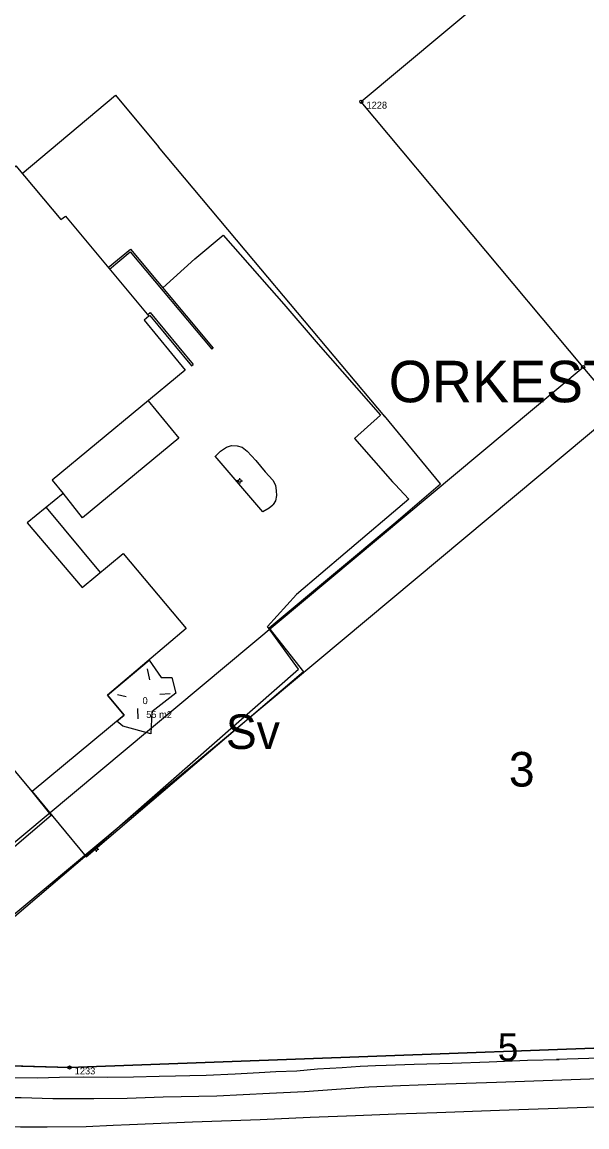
# Model space of a CAD drawing. Extents: x 1517478 to 1518189, y 6494860 to 6495389.
# Drawn here: x 1517838.6 to 1517920.3, y 6494947.7 to 6495107.4 of the extents above; entities that cross this region are included whole.
import ezdxf

# ---------------------------------------------------------------- set-up
doc = ezdxf.new("R2010")
doc.units = 0
for name, color, linetype in [('adress', 7, 'Continuous'), ('allmanbygg_symbollinje', 7, 'Continuous'), ('allmanbyggnad', 7, 'Continuous'), ('allmanbyggnad_nummer', 7, 'Continuous'), ('byggnad_areatext', 7, 'Continuous'), ('fastighetsbeteckning', 7, 'Continuous'), ('gc_vag', 7, 'Continuous'), ('grans', 7, 'Continuous'), ('granspunkt', 7, 'Continuous'), ('granspunkt_text', 7, 'Continuous'), ('kvartersgrans', 7, 'Continuous'), ('kvartersnamn', 7, 'Continuous'), ('kvartersytor', 7, 'Continuous'), ('planteringskant', 7, 'Continuous'), ('rattighet_grans_ANV_EJ', 7, 'Continuous'), ('skarmtak', 7, 'Continuous'), ('staket', 7, 'Continuous'), ('stenmur', 7, 'Continuous'), ('stolpe_belysning', 7, 'Continuous'), ('sv_text', 7, 'Continuous'), ('vagkant', 7, 'Continuous'), ('vagkant_mindre', 7, 'Continuous')]:
    doc.layers.add(name, color=color, linetype=linetype)

msp = doc.modelspace()

# ---------------------------------------------------------------- linework, layer by layer
at = {"layer": 'allmanbygg_symbollinje'}
for p, q in [((1517856.72, 6495013.92), (1517857.04, 6495012.34)), ((1517852.41, 6495010.21), (1517853.68, 6495009.93)), ((1517860.05, 6495010.31), (1517858.55, 6495010.24)), ((1517855.39, 6495006.7), (1517855.36, 6495008.21))]:
    msp.add_line(p, q, dxfattribs=at)
at = {"layer": 'allmanbyggnad'}
for points in [[(1517795.98, 6495052.03), (1517837.72, 6495086.69), (1517844.24, 6495078.9), (1517844.89, 6495079.4), (1517856.96, 6495064.93), (1517856.28, 6495064.33), (1517862.19, 6495057.11), (1517842.98, 6495041.23), (1517844.57, 6495039.29), (1517839.38, 6495035.07), (1517847.33, 6495025.71), (1517853.22, 6495030.6), (1517862.35, 6495019.75), (1517850.98, 6495010.13), (1517853.38, 6495007.24), (1517840.06, 6494996.19), (1517822.37, 6495017.44), (1517823.84, 6495018.69), (1517795.97, 6495052.03)], [(1517850.98, 6495010.13), (1517856.98, 6495015.21), (1517858.75, 6495012.67), (1517860.26, 6495012.67), (1517860.86, 6495010.41), (1517857.4, 6495007.7), (1517857.25, 6495004.55), (1517853.2, 6495005.67), (1517852.31, 6495006.35), (1517853.38, 6495007.24), (1517850.98, 6495010.13)]]:
    msp.add_lwpolyline(points, dxfattribs=at)
at = {"layer": 'gc_vag'}
for points in [[(1517939.93, 6494958.28), (1517936.05, 6494958.14), (1517929.92, 6494957.93), (1517923.68, 6494957.69), (1517915.87, 6494957.44)], [(1517891.25, 6494956.6), (1517889.71, 6494956.53), (1517887.5, 6494956.42), (1517884.91, 6494956.25), (1517881.34, 6494956.04), (1517878.32, 6494955.79), (1517875.31, 6494955.69), (1517872.89, 6494955.51), (1517869.43, 6494955.34), (1517865.22, 6494955.16), (1517862.88, 6494955.09)], [(1517916.26, 6494957.41), (1517911.67, 6494957.3), (1517906.13, 6494957.05), (1517900.78, 6494956.88), (1517895.28, 6494956.74), (1517891.25, 6494956.6)], [(1517862.88, 6494955.09), (1517860.81, 6494955.05), (1517858.46, 6494954.98), (1517854.75, 6494954.91), (1517851, 6494954.84), (1517847.43, 6494954.88), (1517844.03, 6494954.84), (1517840.85, 6494954.74), (1517837.48, 6494954.81), (1517835.56, 6494954.81), (1517834.33, 6494954.91)], [(1517907.22, 6494954.18), (1517920.7, 6494954.64), (1517929.14, 6494954.95), (1517938.99, 6494955.23)], [(1517879.46, 6494952.85), (1517884.07, 6494953.16), (1517888.76, 6494953.52), (1517893.31, 6494953.69), (1517898.43, 6494953.9), (1517907.22, 6494954.18)], [(1517832.31, 6494947.99), (1517832.41, 6494949.71), (1517832.62, 6494951.11), (1517833.29, 6494951.63), (1517833.95, 6494951.95), (1517838.47, 6494951.95), (1517843.09, 6494951.84), (1517849.01, 6494951.84), (1517853.81, 6494951.88)], [(1517853.81, 6494951.88), (1517859.04, 6494952.04), (1517866.75, 6494952.18), (1517874.38, 6494952.57), (1517879.46, 6494952.85)]]:
    msp.add_lwpolyline(points, dxfattribs=at)
at = {"layer": 'grans'}
for p, q in [((1517942.78, 6495142.01), (1517887.66, 6495095.94)), ((1517919.72, 6495057.58), (1517887.66, 6495095.94)), ((1517807.17, 6494963.51), (1517919.72, 6495057.58)), ((1517993.72, 6494969.04), (1517919.72, 6495057.58)), ((1517845.48, 6494956.3), (1517968.3, 6494960.82)), ((1517833.61, 6494956.65), (1517845.48, 6494956.3))]:
    msp.add_line(p, q, dxfattribs=at)
at = {"layer": 'granspunkt'}
for centre in [(1517887.66, 6495095.94), (1517919.72, 6495057.58), (1517845.48, 6494956.3)]:
    msp.add_circle(centre, 0.237, dxfattribs=at)
at = {"layer": 'kvartersgrans'}
msp.add_lwpolyline([(1517810.53, 6494961.99), (1517821.9, 6494958.56), (1517833.61, 6494956.65), (1517845.48, 6494956.3), (1517968.3, 6494960.82), (1517976.46, 6494961.8), (1517984.36, 6494964.1), (1517991.77, 6494967.66)], dxfattribs=at)
at = {"layer": 'kvartersytor'}
msp.add_lwpolyline([(1517905.68, 6495182.68), (1518054.69, 6495019.3), (1517998.49, 6494972.4), (1517993.72, 6494969.04), (1517988.06, 6494965.88), (1517984.36, 6494964.1), (1517976.46, 6494961.8), (1517972.38, 6494961.31), (1517968.3, 6494960.82), (1517845.48, 6494956.3), (1517833.61, 6494956.65)], dxfattribs=at)
at = {"layer": 'planteringskant'}
msp.add_lwpolyline([(1517866.55, 6495044.64), (1517867.32, 6495045.43), (1517868.17, 6495045.97), (1517868.88, 6495046.21), (1517869.72, 6495046.2), (1517870.45, 6495045.97), (1517871.15, 6495045.43), (1517872.4, 6495044.06), (1517873.76, 6495042.4), (1517874.88, 6495041.24), (1517875.25, 6495040.5), (1517875.34, 6495039.67), (1517875.42, 6495039.01), (1517875.24, 6495038.21), (1517874.94, 6495037.7), (1517874.85, 6495037.62), (1517874.35, 6495037.18), (1517873.43, 6495036.64), (1517866.52, 6495044.68)], dxfattribs=at)
at = {"layer": 'rattighet_grans_ANV_EJ'}
msp.add_line((1517924.99, 6495051.56), (1517819.73, 6494963.58), dxfattribs=at)
at = {"layer": 'skarmtak'}
msp.add_line((1517842.08, 6495037.27), (1517849.92, 6495027.86), dxfattribs=at)
msp.add_lwpolyline([(1517856.86, 6495052.71), (1517861.28, 6495047.29), (1517847.36, 6495035.77), (1517844.54, 6495039.33)], dxfattribs=at)
at = {"layer": 'staket'}
for p, q in [((1517872.13, 6495072.97), (1517858.36, 6495089.39)), ((1517891.06, 6495050.42), (1517872.13, 6495072.97)), ((1517874.36, 6495019.87), (1517892.35, 6495034.9)), ((1517879.35, 6495013.53), (1517874.36, 6495019.87)), ((1517847.87, 6494986.76), (1517879.32, 6495013.57)), ((1517840.06, 6494996.19), (1517847.88, 6494986.75))]:
    msp.add_line(p, q, dxfattribs=at)
for points in [[(1517838.64, 6495085.58), (1517852.12, 6495096.88), (1517858.36, 6495089.39)], [(1517892.34, 6495034.89), (1517899.1, 6495040.69), (1517891, 6495050.5)]]:
    msp.add_lwpolyline(points, dxfattribs=at)
at = {"layer": 'stenmur'}
for p, q in [((1517866.03, 6495060.14), (1517866.24, 6495060.33)), ((1517863.11, 6495057.76), (1517863.35, 6495057.96))]:
    msp.add_line(p, q, dxfattribs=at)
for points in [[(1517851.08, 6495071.97), (1517854.28, 6495074.61), (1517866.25, 6495060.32)], [(1517851.26, 6495071.75), (1517854.24, 6495074.21), (1517866.03, 6495060.14)], [(1517856.79, 6495065.18), (1517857.13, 6495065.48), (1517863.35, 6495057.96)], [(1517856.99, 6495064.94), (1517857.09, 6495065.03), (1517863.11, 6495057.76)]]:
    msp.add_lwpolyline(points, dxfattribs=at)
at = {"layer": 'stolpe_belysning'}
for p, q in [((1517869.88, 6495041.12), (1517869.68, 6495041.12)), ((1517870.08, 6495041.32), (1517870.08, 6495041.52)), ((1517870.08, 6495040.92), (1517870.08, 6495040.72)), ((1517870.28, 6495041.12), (1517870.48, 6495041.12)), ((1517849.32, 6494988.07), (1517849.32, 6494988.27)), ((1517849.12, 6494987.87), (1517848.92, 6494987.87)), ((1517849.32, 6494987.67), (1517849.32, 6494987.47)), ((1517849.52, 6494987.87), (1517849.72, 6494987.87))]:
    msp.add_line(p, q, dxfattribs=at)
for centre in [(1517870.08, 6495041.12), (1517849.32, 6494987.87)]:
    msp.add_circle(centre, 0.2, dxfattribs=at)
at = {"layer": 'vagkant'}
for points in [[(1517880.27, 6494949.1), (1517886.83, 6494949.38), (1517892.72, 6494949.59), (1517898.57, 6494949.8), (1517907.64, 6494950.12)], [(1517907.64, 6494950.12), (1517920.28, 6494950.57), (1517928.48, 6494950.89), (1517939.83, 6494951.27)], [(1517854.13, 6494948.06), (1517863.27, 6494948.44), (1517873.02, 6494948.78), (1517880.27, 6494949.1)], [(1517832.31, 6494947.99), (1517834.83, 6494947.82), (1517838.37, 6494947.71), (1517842.24, 6494947.74), (1517847.89, 6494947.75), (1517851.78, 6494947.96), (1517854.13, 6494948.06)]]:
    msp.add_lwpolyline(points, dxfattribs=at)
at = {"layer": 'vagkant_mindre'}
for points in [[(1517858.95, 6495069.04), (1517863.6, 6495073.2), (1517867.67, 6495076.63), (1517876.78, 6495066.27)], [(1517876.44, 6495066.66), (1517881.4, 6495060.9), (1517890.42, 6495050.64), (1517886.67, 6495047.26), (1517892.17, 6495040.97)], [(1517891.87, 6495041.32), (1517894.53, 6495038.47), (1517885.33, 6495030.66), (1517878.31, 6495024.69), (1517874.09, 6495020.04)], [(1517814.6, 6494958.94), (1517835.57, 6494976.43), (1517848.02, 6494987.1), (1517878.6, 6495013.87), (1517874.09, 6495020.04)], [(1517836.85, 6494987.68), (1517842.85, 6494992.77), (1517840.06, 6494996.19)]]:
    msp.add_lwpolyline(points, dxfattribs=at)

# ---------------------------------------------------------------- texts
at = {"layer": 'adress'}
msp.add_text('5', height=4, rotation=0.0021, dxfattribs=at).set_placement((1517907.38, 6494957.24))
at = {"layer": 'allmanbyggnad_nummer'}
msp.add_text('0', height=1, dxfattribs=at).set_placement((1517856.04, 6495008.84))
at = {"layer": 'byggnad_areatext'}
msp.add_text('55 m2', height=1, dxfattribs=at).set_placement((1517856.57, 6495006.84))
at = {"layer": 'fastighetsbeteckning'}
msp.add_text('3', height=5, rotation=0.0021, dxfattribs=at).set_placement((1517908.99, 6494996.92))
at = {"layer": 'granspunkt_text'}
for s, p in [('1228', (1517888.41, 6495094.94)), ('1233', (1517846.23, 6494955.3))]:
    msp.add_text(s, height=1, dxfattribs=at).set_placement(p)
at = {"layer": 'kvartersnamn'}
msp.add_text('ORKESTERN', height=6, rotation=0.0021, dxfattribs=at).set_placement((1517891.62, 6495052.48))
at = {"layer": 'sv_text'}
msp.add_text('Sv', height=5, rotation=0.0021, dxfattribs=at).set_placement((1517868.08, 6495002.35))

doc.saveas('drawing.dxf')
